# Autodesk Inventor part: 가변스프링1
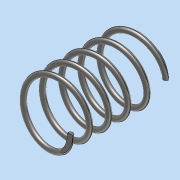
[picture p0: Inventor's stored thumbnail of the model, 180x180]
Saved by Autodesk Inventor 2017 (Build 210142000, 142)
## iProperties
Part Number: 가변스프링1
Material: 강철, 연강
Document SubType Name: Modeling
Designer: MRC
Density: 7.85 g/cm^3
Appearance: 반연마
Mass: 8.42454 g
Surface Area: 21.7273 cm^2
Volume: 1.07319 cm^3
Author: MRC
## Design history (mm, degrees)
sketch "스케치1"
  geometry: L1 (0, 0)-(0, 37.411); L2 (0, 0)-(11, 0); L3 (0, 37.411)-(11, 37.411); C1 r 1 at (11, 0)
  constraints: 6 end point, 2 horizontal, 1 centre point, 1 coincident, 1 vertical
  dimensions: "d0" = 37.4112 distance of L1.start L1.end (derived); "d1" = 11 distance of L1.end L3.end; "d2" = 11 distance of L1.start L2.end; "d3" = 2 diameter of C1
feature "코일1" sketch "스케치1" pitch "d4" = 10; turns "d6" = 5; dims "d5" = 37.4112 (= d0), "d7" = 0, angle "d8" = 90 deg, angle "d9" = 90 deg, "d10" = 0, "d11" = 0
sketch "스케치2"
  geometry: L1 (37.411, 15)-(0, 15); L2 (0, 15)-(0, -15); L3 (0, -15)-(37.411, -15); L4 (37.411, -15)-(37.411, 15); 2 further points
  constraints: 8 end point, 2 parallel, 1 coincident, 1 horizontal, 1 midpoint, 1 perpendicular
  dimensions: "d12" = 37.4112 distance of L2.end L3.end (= d0); "d13" = 30 distance of L3.end L1.start
extrude "돌출1" sketch "스케치2" stored distance "d14" = 0; taper "d15" = 0 deg
node "솔리드1"
